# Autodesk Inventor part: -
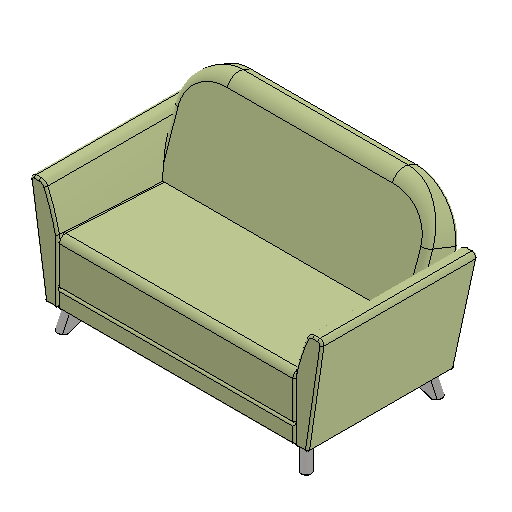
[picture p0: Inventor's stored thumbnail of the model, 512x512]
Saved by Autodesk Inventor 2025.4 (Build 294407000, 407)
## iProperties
Created: 2026-05
Part Number: -
Material: Generic
Description: 2-SEATER
Document SubType Name: Modeling
Designer: Brian.Thangei
Density: 1 g/cm^3
Appearance: Default
Project: HENLEY
Sending System: SolidWorks 2026
Preprocessor: SwSTEP 2.0
Title: Henley 2-Seater.STEP
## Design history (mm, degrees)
feature "NONE"
feature "NONE:1"
feature "NONE:2"
feature "NONE:3"
feature "NONE:4"
feature "NONE:5"
feature "NONE:6"
feature "NONE:7"
feature "NONE:8"
workplane "Work Plane1"
workplane "Work Plane2"
workplane "Work Plane3"
workplane "Work Plane4"
workplane "Work Plane5"
workplane "Work Plane6"
node "Direct Edit1"
node "FOOT"
node "ARM"
node "FOOT2"
node "FOOT3"
node "FOOT4"
node "BASE"
node "ARM2"
node "SEAT"
node "BACK"
move_body "Move1" dims "d0" = 10
move_body "Move2" dims "d3" = -10
other parameters: "d1" = 0, "d2" = 0, "d4" = 0, "d5" = 0
